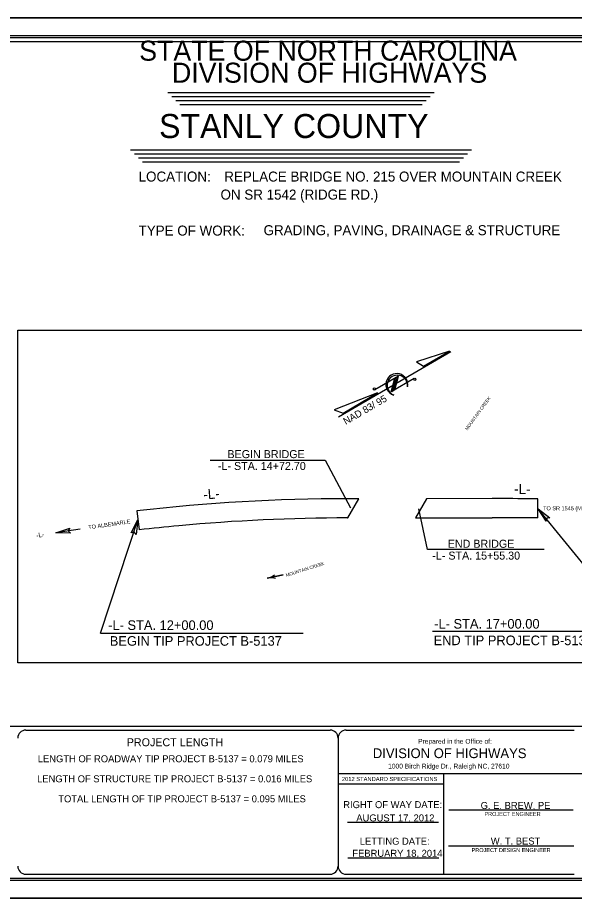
# Model space of a CAD drawing. Extents: x 1664524 to 1666208, y 587901 to 592296.
# Drawn here: x 1665086 to 1665781, y 591186 to 592296 of the extents above; entities that cross this region are included whole.
import ezdxf

# ---------------------------------------------------------------- set-up
doc = ezdxf.new("R2010")
doc.units = 0
for name, color, linetype in [('Default', 7, 'Continuous'), ('Prop Horizontal Alignment', 7, 'Continuous'), ('Prop Horizontal Alignment Station Label', 7, 'Continuous'), ('Prop Horizontal Alignment Tick Label', 7, 'Continuous'), ('Prop Horizontal Alignment Tick Large', 7, 'Continuous'), ('Prop Horizontal Alignment Tick Small', 7, 'Continuous'), ('Prop Terminator CELL', 7, 'Continuous'), ('Sheet Cutting Line CELL', 7, 'Continuous'), ('Sheet North Arrow CELL', 7, 'Continuous')]:
    doc.layers.add(name, color=color, linetype=linetype)

msp = doc.modelspace()

# ---------------------------------------------------------------- linework, layer by layer
at = {"layer": 'Default'}
for p, q in [((1665326.1, 591743.7), (1665469.7, 591743.7)), ((1665469.7, 591743.7), (1665501.2, 591684.1)), ((1665511.7, 591695.5), (1665497.5, 591695.5)), ((1665497.8, 591671.5), (1665511.7, 591695.5)), ((1665596.2, 591695.5), (1665582.4, 591671.5)), ((1665678.2, 591695.6), (1665596.2, 591695.5)), ((1665735.3, 591671.4), (1665735.5, 591695.2)), ((1665234.6, 591680.2), (1665237.3, 591656.7)), ((1665597.5, 591631.9), (1665586.6, 591682.8)), ((1665860.9, 591529.4), (1665735.9, 591682.8)), ((1665189, 591527.7), (1665235.8, 591669.2)), ((1665497.5, 591671.5), (1665497.8, 591671.5)), ((1665582.4, 591671.5), (1665678.2, 591671.6)), ((1665163.5, 591657.3), (1665133.3, 591652.9)), ((1665743.4, 591631.9), (1665597.5, 591631.9)), ((1665407.2, 591598.3), (1665407.2, 591598.3)), ((1665189, 591527.7), (1665442.3, 591527.6)), ((1665860.9, 591529.4), (1665603.8, 591529.4))]:
    msp.add_line(p, q, dxfattribs=at)
msp.add_lwpolyline([(1665085.7, 591906.1), (1666081.5, 591906.1), (1666081.5, 591490.5), (1665085.7, 591490.5)], close=True, dxfattribs=at)
for points in [[(1665685.3, 591671.6), (1665685.3, 591671.6)], [(1665407.7, 591596), (1665405.7, 591596.4), (1665403.6, 591596.7), (1665401.5, 591596.7), (1665399.5, 591596.7), (1665397.4, 591596.3), (1665417.1, 591600.2), (1665397.4, 591596.3), (1665399.4, 591596.8), (1665401.4, 591597.5), (1665403.3, 591598.4), (1665405.1, 591599.4), (1665406.8, 591600.5)]]:
    msp.add_lwpolyline(points, dxfattribs=at)
for centre, radius, start, end in [((1665498.3, 589413.5), 2282, 90.0196, 96.6366), ((1665680.9, 583683.6), 8012, 89.96761, 90.01962), ((1665653.2, 583683.7), 8012, 89.41172, 89.76928), ((1665498.3, 589413.5), 2258, 90.0196, 95.3678), ((1665680.9, 583683.6), 7988, 89.96868, 90.01962), ((1665682.6, 583683.6), 7988, 89.62225, 89.98089), ((1665484.1, 589412), 2258.2, 95.0059, 96.2747)]:
    msp.add_arc(centre, radius, start, end, dxfattribs=at)
at = {"layer": 'Prop Horizontal Alignment Station Label'}
for p, q in [((1665273.2, 592202.8), (1665605.9, 592202.8)), ((1665278.2, 592197.8), (1665600.9, 592197.8)), ((1665283.2, 592192.8), (1665595.9, 592192.8)), ((1665288.2, 592187.8), (1665590.9, 592187.8)), ((1665226.5, 592131.2), (1665652.5, 592131.2)), ((1665231.5, 592126.2), (1665647.5, 592126.2)), ((1665236.5, 592121.2), (1665642.5, 592121.2)), ((1665241.5, 592116.2), (1665637.5, 592116.2)), ((1664755.8, 591411.3), (1666175.8, 591411.3)), ((1665095.8, 591406.3), (1665475.8, 591406.3)), ((1665495.8, 591406.3), (1665780.8, 591406.3)), ((1665485.8, 591396.3), (1665485.8, 591236.3)), ((1665790.8, 591351.6), (1665485.8, 591351.6)), ((1665617.3, 591351.6), (1665617.3, 591226.3)), ((1665617.3, 591338.8), (1665485.8, 591338.8)), ((1665579.4, 591338.8), (1665579.4, 591338.8)), ((1665624.2, 591306.6), (1665779.4, 591306.6)), ((1665611.3, 591291), (1665497.6, 591291)), ((1665554.4, 591291), (1665554.4, 591291)), ((1665623.9, 591261.6), (1665780.1, 591261.6)), ((1665611.7, 591246.4), (1665498, 591246.4))]:
    msp.add_line(p, q, dxfattribs=at)
for points in [[(1666180.8, 592271.3), (1664700.7, 592271.3)], [(1666175.8, 592266.3), (1664755.8, 592266.3)], [(1665095.8, 591226.3), (1665475.8, 591226.3)], [(1665495.8, 591226.3), (1665780.8, 591226.3)], [(1664700.8, 591221.3), (1666180.8, 591221.3)]]:
    msp.add_lwpolyline(points, dxfattribs=at)
for centre, start, end in [((1665095.8, 591396.4), 90, 180), ((1665475.8, 591396.4), 0, 90), ((1665495.8, 591396.4), 90, 180), ((1665095.8, 591236.4), 180, 270), ((1665475.8, 591236.4), 270, 360), ((1665495.8, 591236.4), 180, 270)]:
    msp.add_arc(centre, 10, start, end, dxfattribs=at)
at = {"layer": 'Prop Horizontal Alignment Tick Label'}
for p, q in [((1665441.1, 592146.1), (1665441.1, 592146.1)), ((1665561.1, 592091.7), (1665561.1, 592091.7))]:
    msp.add_line(p, q, dxfattribs=at)
at = {"layer": 'Prop Horizontal Alignment Tick Large'}
msp.add_lwpolyline([(1664536.8, 591218.8), (1666203.3, 591218.8), (1666203.3, 592273.9), (1664536.8, 592273.9)], close=True, dxfattribs=at)
at = {"layer": 'Prop Horizontal Alignment Tick Small'}
for points in [[(1666207.8, 592296.3), (1664523.8, 592296.3), (1664523.8, 591196.3), (1666207.8, 591196.3)], [(1664523.8, 590101.3), (1666207.3, 590101.3), (1666207.3, 591196.3), (1664523.8, 591196.3)]]:
    msp.add_lwpolyline(points, close=True, dxfattribs=at)
at = {"layer": 'Prop Terminator CELL'}
for points in [[(1665745.8, 591667.4), (1665735.9, 591682.8), (1665750.5, 591671.6), (1665746.6, 591671.2)], [(1665227.5, 591652.9), (1665235.8, 591669.2), (1665233.5, 591650.9), (1665231.1, 591654.1)], [(1665151.6, 591652.4), (1665133.3, 591652.9), (1665150.7, 591658.7), (1665148.9, 591655.2)]]:
    msp.add_lwpolyline(points, close=True, dxfattribs=at)
at = {"layer": 'Sheet Cutting Line CELL'}
for p, q in [((1664523.8, 592296.3), (1666207.8, 592296.3)), ((1664523.8, 591196.3), (1666207.8, 591196.3)), ((1666207.3, 591196.3), (1664523.8, 591196.3))]:
    msp.add_line(p, q, dxfattribs=at)
at = {"layer": 'Sheet North Arrow CELL'}
for p, q in [((1665486.4, 591797.6), (1665626.7, 591879.6)), ((1665561.1, 591848.6), (1665531.9, 591831.5)), ((1665552.2, 591828.9), (1665556.7, 591845.9)), ((1665581, 591845.8), (1665552.2, 591828.9)), ((1665553, 591829.4), (1665557.5, 591846.4)), ((1665557.5, 591846.4), (1665553, 591829.4)), ((1665555.6, 591831), (1665560.1, 591847.9)), ((1665556.7, 591831.6), (1665561.1, 591848.6)), ((1665560.1, 591847.9), (1665557.5, 591846.4)), ((1665572.6, 591835.5), (1665572.6, 591835.3)), ((1665553, 591829.4), (1665555.6, 591831))]:
    msp.add_line(p, q, dxfattribs=at)
for points in [[(1665624.9, 591879.8), (1665583.8, 591866.6), (1665592.6, 591860.9)], [(1665535.2, 591827.6), (1665481.1, 591806.7), (1665492, 591802.4)]]:
    msp.add_lwpolyline(points, close=True, dxfattribs=at)
for centre in [(1665581.6, 591844.6), (1665531.2, 591832.6)]:
    msp.add_circle(centre, 1.32, dxfattribs=at)
for centre, radius, start, end in [((1665559.2, 591838.1), 13.7, 348.1215, 252.6755), ((1665559.9, 591837), 12.8, 353.3765, 248.9101)]:
    msp.add_arc(centre, radius, start, end, dxfattribs=at)

# ---------------------------------------------------------------- texts
at = {"layer": 'Default'}
for s, height, rotation, p in [(' MOUNTAIN CREEK', 4, 54.1437, (1665646.5, 591779.3)), ('-L-', 12.5, 359.5396, (1665705.7, 591701.5)), ('-L-', 12.5, 4.5198, (1665318, 591694.4)), ('TO ALBEMARLE', 5, 8.0831, (1665174.2, 591657.2)), ('-L-', 6, 10.3687, (1665109.4, 591646.4)), (' MOUNTAIN CREEK', 4, 17.5368, (1665419.8, 591597.4))]:
    msp.add_text(s, height=height, rotation=rotation, dxfattribs=at).set_placement(p)
for s, height, p in [('BEGIN BRIDGE', 10, (1665347.6, 591746.2)), ('-L- STA. 14+72.70', 10, (1665335.8, 591731.4)), ('TO SR 1545 (MOUNTAIN VIEW CHURCH RD.)', 5, (1665741.9, 591681)), ('END BRIDGE', 10, (1665622.8, 591634.2)), ('-L- STA. 15+55.30', 10, (1665603.5, 591619.4)), ('-L- STA. 12+00.00', 12, (1665198.7, 591531.5)), ('-L- STA. 17+00.00', 12, (1665605.9, 591533.2)), ('BEGIN TIP PROJECT B-5137', 12, (1665200.7, 591511.8)), ('END TIP PROJECT B-5137', 12, (1665605.1, 591512.5))]:
    msp.add_text(s, height=height, dxfattribs=at).set_placement(p)
at = {"layer": 'Prop Horizontal Alignment'}
for s, height, p in [('STANLY COUNTY', 30, (1665262.2, 592146.1)), (' REPLACE BRIDGE NO. 215 OVER MOUNTAIN CREEK', 12.5, (1665339, 592091.7)), ('ON SR 1542 (RIDGE RD.)', 12.5, (1665339, 592069.2)), ('GRADING, PAVING, DRAINAGE & STRUCTURE', 12.5, (1665392.8, 592024.7)), ('LENGTH OF ROADWAY TIP PROJECT B-5137 = 0.079 MILES', 8.75, (1665110.8, 591366.2)), ('LENGTH OF STRUCTURE TIP PROJECT B-5137 = 0.016 MILES', 8.75, (1665109.9, 591341.2)), ('TOTAL LENGTH OF TIP PROJECT B-5137 = 0.095 MILES', 8.75, (1665136.4, 591316.2)), ('G. E. BREW, PE', 8.75, (1665663.9, 591307.9)), ('AUGUST 17, 2012', 8.75, (1665508.6, 591292.3)), ('W. T. BEST', 8.75, (1665676.6, 591263.4)), ('FEBRUARY 18, 2014', 8.75, (1665503.7, 591248.1))]:
    msp.add_text(s, height=height, dxfattribs=at).set_placement(p)
at = {"layer": 'Prop Horizontal Alignment Station Label'}
for s, height, p in [('STATE OF NORTH CAROLINA', 25, (1665237.4, 592242.7)), ('DIVISION OF HIGHWAYS', 25, (1665278.3, 592215.2)), ('LOCATION: ', 12.5, (1665236.7, 592091.7)), ('TYPE OF WORK:', 12.5, (1665236.7, 592024.2)), ('PROJECT LENGTH', 10, (1665221.9, 591386.2)), ('Prepared in the Office of:', 5.999, (1665585.8, 591389.4)), ('DIVISION OF HIGHWAYS', 12.187, (1665529.2, 591371.4)), ('1000 Birch Ridge Dr., Raleigh NC, 27610', 6, (1665548.4, 591358.4)), ('RIGHT OF WAY DATE: ', 8.75, (1665492.3, 591308.9)), ('PROJECT ENGINEER', 5, (1665668.6, 591299.1)), ('LETTING DATE:', 8.75, (1665513, 591263.2)), ('PROJECT DESIGN ENGINEER', 5, (1665652.6, 591254))]:
    msp.add_text(s, height=height, rotation=360, dxfattribs=at).set_placement(p)
msp.add_text('2012 STANDARD SPECIFICATIONS', height=5.2, dxfattribs=at).set_placement((1665490.6, 591342.7))
at = {"layer": 'Sheet North Arrow CELL'}
msp.add_text('NAD 83/ 95', height=8.75, rotation=30.2814, dxfattribs=at).set_placement((1665495.5, 591787.5))

doc.saveas('drawing.dxf')
